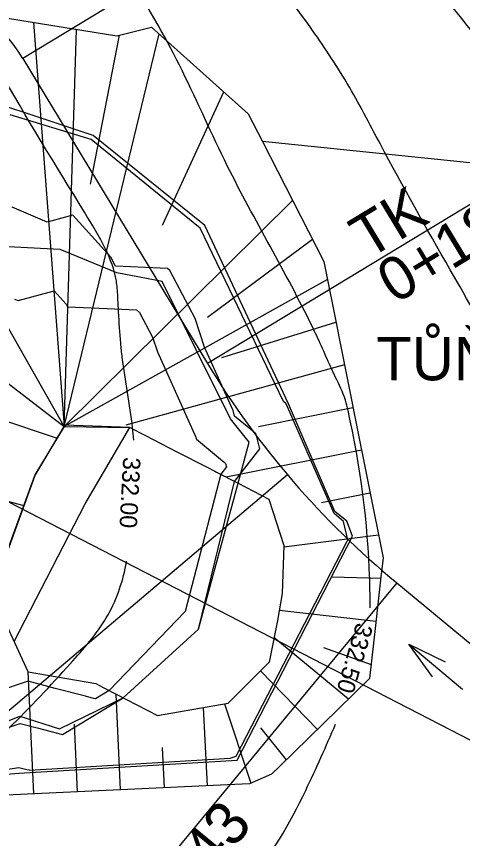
# Model space of a CAD drawing. Extents: x -564037 to -563827, y -1163561 to -1163412.
# Drawn here: x -563856.32 to -563843.49, y -1163511.75 to -1163488.1 of the extents above; entities that cross this region are included whole.
import ezdxf

# ---------------------------------------------------------------- set-up
doc = ezdxf.new("R2010")
doc.units = 0
for name, color, linetype in [('4', 7, 'Continuous'), ('5', 7, 'Continuous'), ('_popis staničení RT1', 7, 'Continuous'), ('Default', 7, 'Continuous'), ('Line', 7, 'Continuous'), ('podélný profil', 7, 'Continuous'), ('Vrstva 24', 7, 'Continuous'), ('Vrstva 25', 7, 'Continuous'), ('Vrstva 26', 7, 'Continuous')]:
    doc.layers.add(name, color=color, linetype=linetype)

msp = doc.modelspace()

# ---------------------------------------------------------------- linework, layer by layer
msp.add_lwpolyline([(-563864.657, -1163510.241), (-563863.634, -1163509.902), (-563862.371, -1163510.364), (-563856.258, -1163509.872), (-563849.971, -1163509.495), (-563846.657, -1163503.058), (-563846.814, -1163502.626), (-563847.162, -1163502.341), (-563848.492, -1163499.244), (-563850.901, -1163494.112), (-563854.114, -1163491.532), (-563858.451, -1163490.091), (-563858.61, -1163489.95), (-563858.72, -1163489.955), (-563860.965, -1163495.118), (-563861.68, -1163496.963), (-563862.247, -1163498.693), (-563862.652, -1163500.191), (-563862.88, -1163501.229), (-563863.177, -1163502.77), (-563863.416, -1163504.013), (-563864.472, -1163509.23)], close=True)
for points in [[(-563835.323, -1163497.175), (-563841.877, -1163492.459), (-563849.248, -1163491.704)], [(-563857.372, -1163508.823), (-563856.219, -1163508.439), (-563855.729, -1163508.568), (-563855.181, -1163508.711), (-563855.038, -1163508.748), (-563855.001, -1163508.758), (-563853.257, -1163507.7), (-563851.082, -1163505.728), (-563850.049, -1163501.478), (-563849.317, -1163500.542), (-563849.427, -1163500.115), (-563849.458, -1163500.089), (-563849.578, -1163499.989), (-563850.046, -1163499.6), (-563850.092, -1163499.443), (-563850.095, -1163499.421), (-563850.911, -1163497.612), (-563851.181, -1163496.789), (-563851.911, -1163495.41), (-563851.978, -1163495.349), (-563852.615, -1163495.322), (-563853.472, -1163495.285), (-563853.605, -1163495.027), (-563854.706, -1163493.822), (-563855.435, -1163494.017), (-563856.443, -1163493.586)], [(-563851.082, -1163505.728), (-563849.948, -1163501.531), (-563849.628, -1163500.347), (-563850.165, -1163499.681), (-563852.128, -1163495.731), (-563853.44, -1163495.48), (-563855.061, -1163494.806), (-563857.328, -1163494.696), (-563858.771, -1163495.906), (-563860.007, -1163498.17), (-563860.512, -1163500.673), (-563860.896, -1163502.23)], [(-563856.379, -1163496.234), (-563856.277, -1163496.278), (-563855.24, -1163496), (-563854.896, -1163496.377), (-563854.855, -1163496.458), (-563853.717, -1163496.506), (-563852.871, -1163496.541), (-563852.783, -1163496.623), (-563852.407, -1163497.332), (-563852.268, -1163497.755), (-563851.164, -1163500.203), (-563851.163, -1163500.211), (-563851.147, -1163500.265), (-563850.512, -1163500.793), (-563850.349, -1163500.928), (-563850.307, -1163500.963), (-563850.282, -1163501.06), (-563850.448, -1163501.273), (-563851.472, -1163505.217), (-563853.656, -1163507.495), (-563854.052, -1163507.735), (-563854.111, -1163507.72), (-563854.338, -1163507.66), (-563855.207, -1163507.433), (-563855.986, -1163507.229), (-563857.817, -1163507.837)], [(-563856.388, -1163506.086), (-563854.345, -1163502.122), (-563853.059, -1163499.927), (-563853.059, -1163499.927), (-563854.941, -1163499.862), (-563854.943, -1163499.866), (-563854.945, -1163499.871), (-563854.945, -1163499.872), (-563854.945, -1163499.872), (-563854.946, -1163499.874), (-563854.947, -1163499.877), (-563854.947, -1163499.882), (-563854.948, -1163499.885), (-563854.948, -1163499.887), (-563854.949, -1163499.892), (-563854.949, -1163499.893), (-563854.949, -1163499.897), (-563855.795, -1163501.288), (-563855.796, -1163501.294), (-563855.797, -1163501.299), (-563855.798, -1163501.305), (-563855.799, -1163501.31), (-563855.799, -1163501.31), (-563855.8, -1163501.316), (-563855.8, -1163501.316), (-563855.801, -1163501.321), (-563855.802, -1163501.327), (-563855.803, -1163501.332), (-563855.804, -1163501.337), (-563855.804, -1163501.338), (-563855.805, -1163501.338), (-563857.031, -1163504.7)], [(-563855.984, -1163506.959), (-563857.031, -1163504.7), (-563857.031, -1163504.7), (-563856.418, -1163503.019), (-563856.418, -1163503.019), (-563855.805, -1163501.338), (-563854.949, -1163499.897), (-563853.059, -1163499.927), (-563853.059, -1163499.927), (-563852.615, -1163500.156), (-563851.726, -1163500.614), (-563850.837, -1163501.073), (-563850.62, -1163501.184), (-563850.566, -1163501.212), (-563849.948, -1163501.531), (-563849.059, -1163501.989), (-563848.632, -1163503.326), (-563848.683, -1163504.7), (-563848.816, -1163505.479), (-563849.057, -1163506.682), (-563849.057, -1163506.682)], [(-563860.896, -1163502.23), (-563862.024, -1163503.851), (-563862.248, -1163505.159), (-563862.261, -1163506.3), (-563861.956, -1163507.245), (-563860.98, -1163508.524), (-563858.933, -1163508.555), (-563858.491, -1163508.894), (-563856.971, -1163508.532), (-563856.225, -1163508.234), (-563855.087, -1163508.595), (-563853.257, -1163507.7), (-563851.082, -1163505.728)], [(-563855.984, -1163506.959), (-563855.984, -1163506.959), (-563855.984, -1163506.959), (-563854.044, -1163507.294), (-563853.828, -1163507.406), (-563853.773, -1163507.434), (-563853.155, -1163507.753), (-563852.267, -1163508.211), (-563850.237, -1163507.862), (-563849.057, -1163506.682)]]:
    msp.add_lwpolyline(points)
at = {"layer": '5'}
for p, q in [((-563856.14, -1163489.312), (-563850.828, -1163498.085)), ((-563871.424, -1163494.398), (-563841.172, -1163509.993)), ((-563845.378, -1163504.4), (-563840.311, -1163508.591))]:
    msp.add_line(p, q, dxfattribs=at)
for centre, radius, start, end in [((-563860.417, -1163491.902), 5, 31.1947, 118.6163), ((-563829.443, -1163485.136), 25, 211.1947, 230.4029)]:
    msp.add_arc(centre, radius, start, end, dxfattribs=at)
at = {"layer": '_popis staničení RT1'}
for points in [[(-563846.118, -1163483.244), (-563856.14, -1163489.312)], [(-563840.579, -1163491.879), (-563850.828, -1163498.085)], [(-563848.524, -1163501.289), (-563868.873, -1163518.515)], [(-563845.378, -1163504.4), (-563854.938, -1163515.958)]]:
    msp.add_lwpolyline(points, dxfattribs=at)
at = {"layer": 'Default'}
for points in [[(-563856.89, -1163488.106), (-563853.44, -1163488.662), (-563853.44, -1163488.662), (-563852.435, -1163488.408), (-563849.66, -1163490.902), (-563849.248, -1163491.704), (-563847.479, -1163495.149), (-563847.069, -1163497.206), (-563847.056, -1163497.268), (-563846.963, -1163497.738), (-563846.685, -1163499.13), (-563846.607, -1163499.521), (-563845.777, -1163503.681), (-563845.837, -1163504.223), (-563845.992, -1163505.619), (-563846.162, -1163507.148), (-563847.068, -1163508.033), (-563848.757, -1163509.681), (-563848.985, -1163509.903), (-563849.622, -1163510.18), (-563850.252, -1163510.208), (-563856.616, -1163510.499)], [(-563858.576, -1163510.061), (-563856.251, -1163509.704), (-563856.025, -1163509.763), (-563855.966, -1163509.779), (-563855.951, -1163509.783), (-563850.176, -1163509.436), (-563849.999, -1163509.38), (-563846.819, -1163503.213), (-563846.792, -1163503.158), (-563846.911, -1163502.63), (-563847.181, -1163502.402), (-563848.566, -1163499.249), (-563848.643, -1163499.184), (-563851.038, -1163494.195), (-563851.083, -1163494.154), (-563854.17, -1163491.64), (-563856.508, -1163490.933)]]:
    msp.add_lwpolyline(points, dxfattribs=at)
at = {"layer": 'Line'}
for p, q in [((-563855.832, -1163488.276), (-563854.949, -1163499.897)), ((-563854.949, -1163499.897), (-563854.598, -1163488.475)), ((-563854.949, -1163499.897), (-563852.219, -1163488.602)), ((-563853.365, -1163488.643), (-563854.202, -1163492.931)), ((-563852.12, -1163494.109), (-563850.359, -1163490.274)), ((-563854.949, -1163499.897), (-563859.159, -1163492.49)), ((-563848.377, -1163493.402), (-563854.949, -1163499.897)), ((-563850.823, -1163496.757), (-563847.806, -1163494.514)), ((-563847.374, -1163495.674), (-563854.949, -1163499.897)), ((-563860.099, -1163495.962), (-563854.949, -1163499.897)), ((-563850.414, -1163497.915), (-563847.13, -1163496.9)), ((-563846.885, -1163498.126), (-563853.181, -1163499.864)), ((-563860.92, -1163498.323), (-563855.149, -1163500.234)), ((-563849.357, -1163499.894), (-563846.641, -1163499.352)), ((-563846.396, -1163500.578), (-563850.29, -1163501.354)), ((-563861.612, -1163500.724), (-563856.108, -1163502.17)), ((-563847.546, -1163502.082), (-563846.152, -1163501.804)), ((-563845.907, -1163503.029), (-563848.634, -1163503.372)), ((-563847.253, -1163504.222), (-563845.842, -1163504.263)), ((-563845.979, -1163505.505), (-563848.768, -1163505.196)), ((-563846.768, -1163507.74), (-563848.915, -1163505.971)), ((-563847.494, -1163506.252), (-563846.117, -1163506.748)), ((-563855.823, -1163510.463), (-563855.984, -1163506.959)), ((-563849.305, -1163506.93), (-563847.663, -1163508.613)), ((-563853.326, -1163510.349), (-563853.452, -1163507.6)), ((-563850.341, -1163507.88), (-563849.583, -1163510.163)), ((-563850.829, -1163510.235), (-563850.945, -1163507.984)), ((-563854.664, -1163508.463), (-563854.575, -1163510.406)), ((-563848.557, -1163509.486), (-563849.294, -1163508.571)), ((-563852.131, -1163509.129), (-563852.077, -1163510.292))]:
    msp.add_line(p, q, dxfattribs=at)
at = {"layer": 'podélný profil'}
for points in [[(-563844.352, -1163507.099), (-563845.039, -1163506.16), (-563843.991, -1163506.665)], [(-563845.039, -1163506.16), (-563843.489, -1163507.451)]]:
    msp.add_lwpolyline(points, dxfattribs=at)
at = {"layer": 'Vrstva 24'}
for points in [[(-563834.56, -1163494.639), (-563836.366, -1163491.682), (-563837.263, -1163490.402), (-563838.091, -1163489.323), (-563838.932, -1163488.255), (-563840.679, -1163486.176), (-563843.599, -1163482.931), (-563845.377, -1163480.993), (-563847.69, -1163478.523), (-563848.871, -1163477.312), (-563850.082, -1163476.13), (-563853.183, -1163473.259), (-563856.324, -1163470.434), (-563856.74, -1163470.064), (-563856.896, -1163469.927), (-563857.179, -1163469.672), (-563858.782, -1163468.194), (-563860.374, -1163466.704), (-563861.969, -1163465.217), (-563862.806, -1163464.448)], [(-563852.947, -1163500.287), (-563852.983, -1163499.934), (-563853.278, -1163497.907), (-563853.324, -1163497.501), (-563853.384, -1163496.604), (-563853.408, -1163496.155), (-563853.449, -1163495.707), (-563853.76, -1163494.797), (-563854.364, -1163493.737), (-563856.816, -1163489.636), (-563859.313, -1163485.439), (-563859.915, -1163484.694), (-563860.397, -1163484.207), (-563862.509, -1163482.09), (-563867.011, -1163477.664), (-563868.116, -1163476.702), (-563871.116, -1163474.41), (-563872.986, -1163473.06), (-563873.689, -1163472.566), (-563878.103, -1163469.411), (-563878.316, -1163469.26)], [(-563840.258, -1163509.873), (-563839.896, -1163508.143), (-563839.904, -1163507.091), (-563840.452, -1163504.683), (-563840.841, -1163503.06), (-563841.044, -1163502.221), (-563841.512, -1163500.521), (-563841.78, -1163499.679), (-563842.064, -1163498.842), (-563842.395, -1163498.068), (-563843.845, -1163495.39), (-563845.853, -1163491.78), (-563846.807, -1163490.032), (-563847.876, -1163488.404), (-563852.123, -1163483.19), (-563853.868, -1163481.341), (-563857.18, -1163478.245), (-563858.504, -1163477.011), (-563860.386, -1163475.26)], [(-563889.716, -1163520.8), (-563887.224, -1163519.911), (-563886.24, -1163519.498), (-563885.546, -1163519.209), (-563880.746, -1163517.448), (-563876.224, -1163515.756), (-563875.074, -1163515.432), (-563873.084, -1163514.978), (-563867.347, -1163513.297), (-563865.289, -1163512.648), (-563863.244, -1163511.964), (-563861.209, -1163511.247), (-563859.18, -1163510.499), (-563858.534, -1163510.142), (-563854.776, -1163506.721), (-563853.738, -1163505.401), (-563853.175, -1163503.886), (-563853.155, -1163503.776)]]:
    msp.add_spline(points, degree=3, dxfattribs=at)
at = {"layer": 'Vrstva 26'}
for points in [[(-563838.029, -1163497.163), (-563838.58, -1163496.19), (-563840.28, -1163493.165), (-563841.199, -1163491.578), (-563841.674, -1163490.793), (-563842.159, -1163490.013), (-563843.649, -1163487.993), (-563844.702, -1163486.757), (-563850.461, -1163480.038), (-563851.089, -1163479.371), (-563851.956, -1163478.574), (-563857.613, -1163473.501), (-563859.731, -1163471.636), (-563864.022, -1163468.083), (-563864.562, -1163467.631), (-563865.045, -1163467.216), (-563865.679, -1163466.68)], [(-563830.975, -1163492.455), (-563831.969, -1163491.156), (-563833.366, -1163489.371), (-563836.213, -1163485.841), (-563837.542, -1163484.256), (-563839.463, -1163482.209), (-563842.521, -1163479.096), (-563847.489, -1163473.999), (-563848.959, -1163472.514), (-563850.05, -1163471.5)], [(-563846.143, -1163505.119), (-563846.16, -1163504.298), (-563846.784, -1163499.435), (-563846.859, -1163499.141), (-563847.15, -1163498.47), (-563847.685, -1163497.291), (-563847.809, -1163497.032), (-563850.257, -1163492.396), (-563853.06, -1163487.093), (-563853.131, -1163486.997), (-563856.933, -1163483.04), (-563859.434, -1163480.56), (-563863.484, -1163476.533), (-563865.168, -1163474.917), (-563866.123, -1163474.143), (-563868.988, -1163472.112)], [(-563884.303, -1163523.029), (-563883.245, -1163522.781), (-563881.496, -1163522.368), (-563879.757, -1163521.916), (-563878.567, -1163521.564), (-563877.835, -1163521.362), (-563875.123, -1163520.885), (-563873.76, -1163520.686), (-563872.402, -1163520.46), (-563869.112, -1163519.839), (-563866.602, -1163519.331), (-563861.504, -1163518.34), (-563860.526, -1163518.047), (-563857.854, -1163516.895), (-563851.038, -1163513.844), (-563850.072, -1163513.304), (-563849.729, -1163513.002), (-563848.002, -1163510.368), (-563847.142, -1163508.464)]]:
    msp.add_spline(points, degree=3, dxfattribs=at)

# ---------------------------------------------------------------- texts
at = {"layer": '4'}
msp.add_text('TŮŇ T4', height=1.25, rotation=360, dxfattribs=at).set_placement((-563845.97, -1163498.57))
at = {"layer": '_popis staničení RT1'}
for s, rotation, p in [('0+183.05', 31.1947, (-563845.435, -1163496.392)), ('TK ', 31.1947, (-563846.212, -1163495.109)), ('0+191.43', 50.4029, (-563853.975, -1163516.755))]:
    msp.add_text(s, height=1.25, rotation=rotation, dxfattribs=at).set_placement(p)
at = {"layer": 'Vrstva 25'}
for s, rotation, p in [('332.00', 266.9159, (-563853.25, -1163500.767)), ('332.50', 253.5078, (-563846.537, -1163505.516))]:
    msp.add_text(s, height=0.5, rotation=rotation, dxfattribs=at).set_placement(p)

doc.saveas('drawing.dxf')
